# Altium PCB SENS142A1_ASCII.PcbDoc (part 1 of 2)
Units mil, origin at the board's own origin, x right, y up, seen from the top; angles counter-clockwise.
Board outline 2760 x 2518.85 mil, 4 copper layers (Top Layer, Signal Layer 1, Signal Layer 2, Bottom Layer), stack 62.2 mil thick; 50 components, 21 nets, 98 pads, 258 vias.
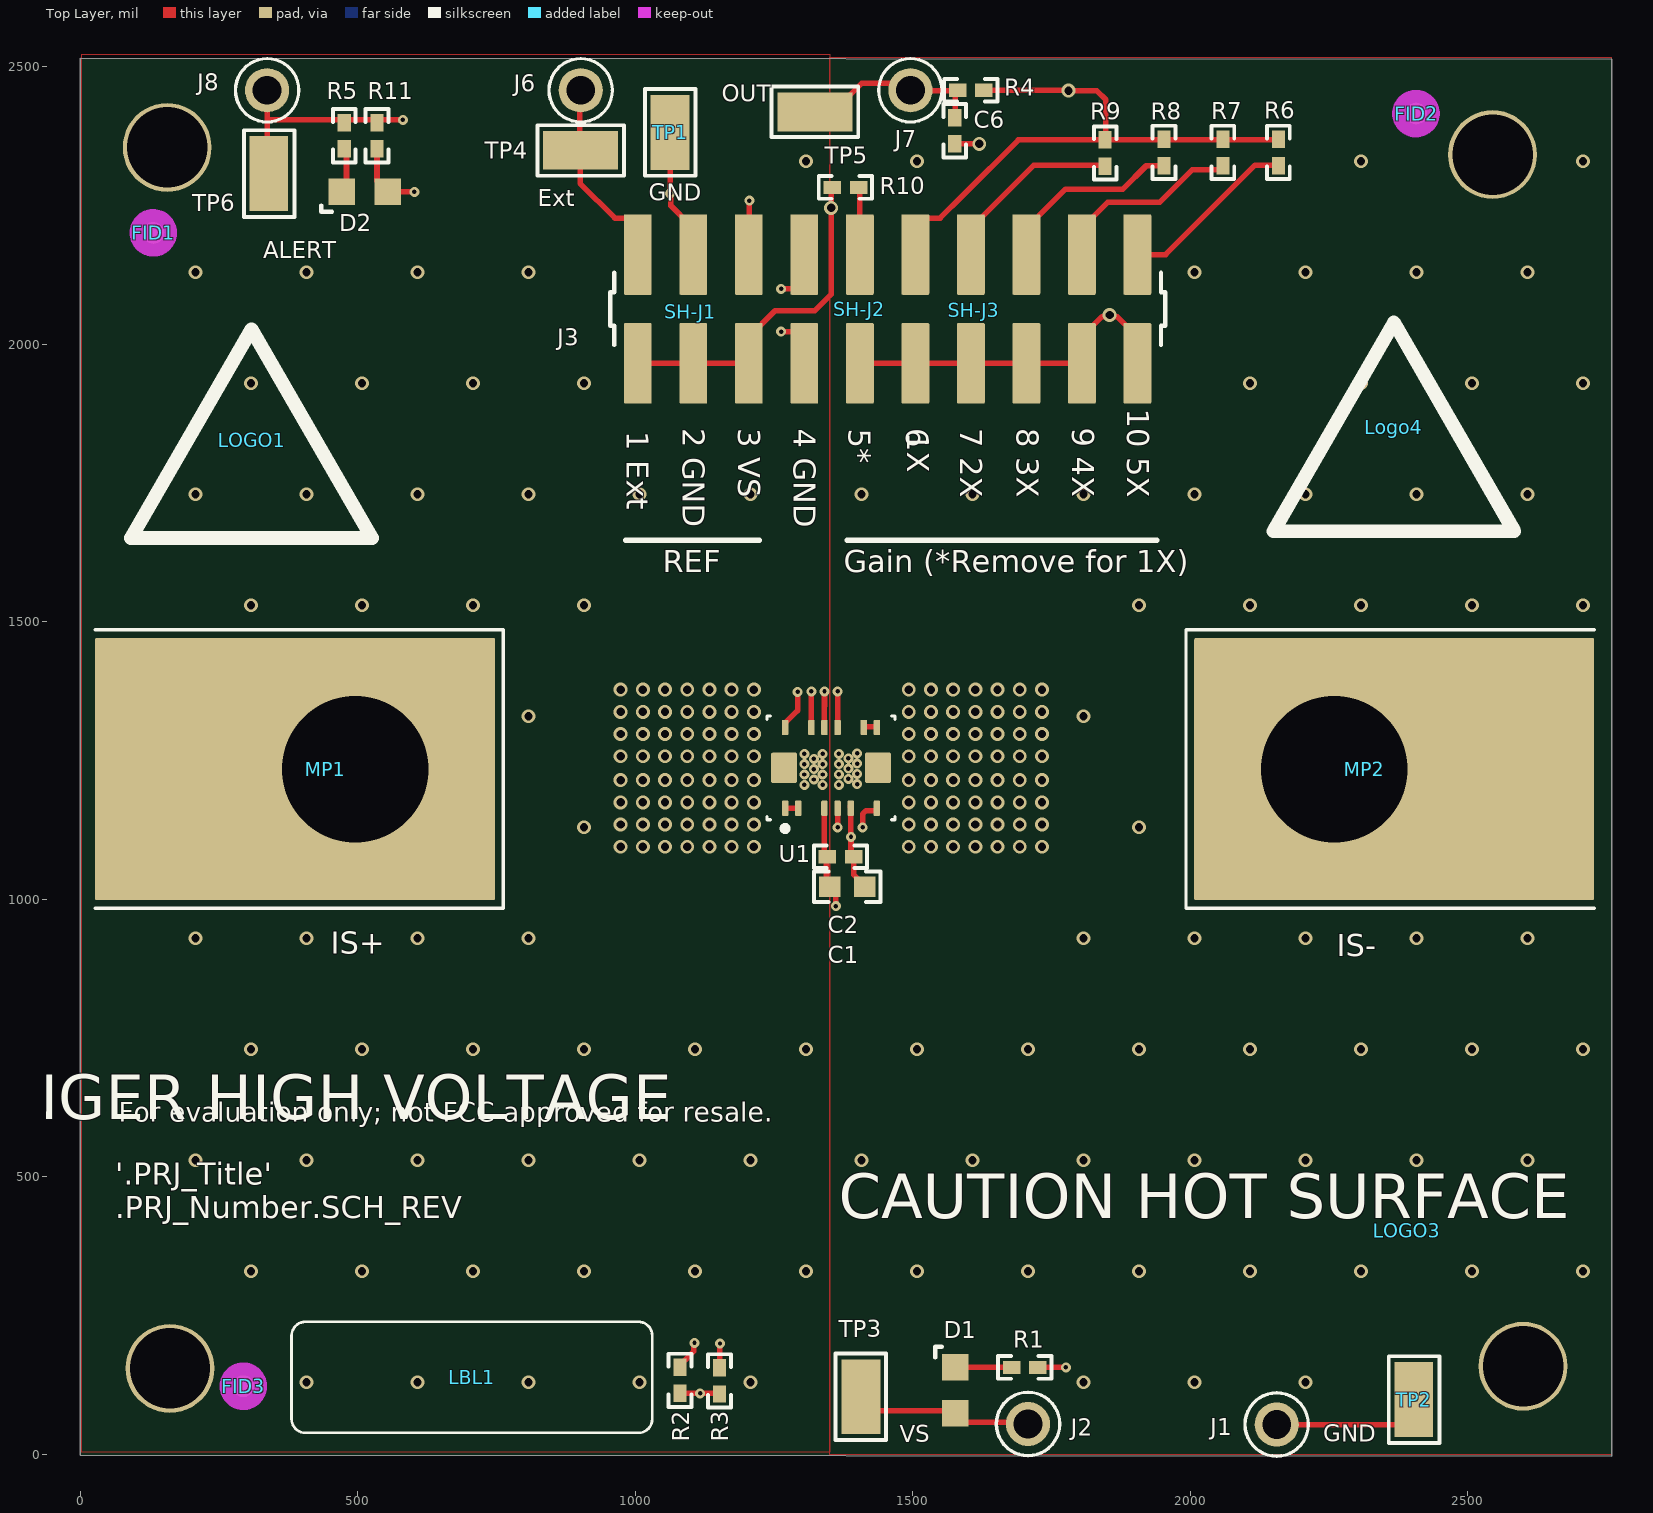
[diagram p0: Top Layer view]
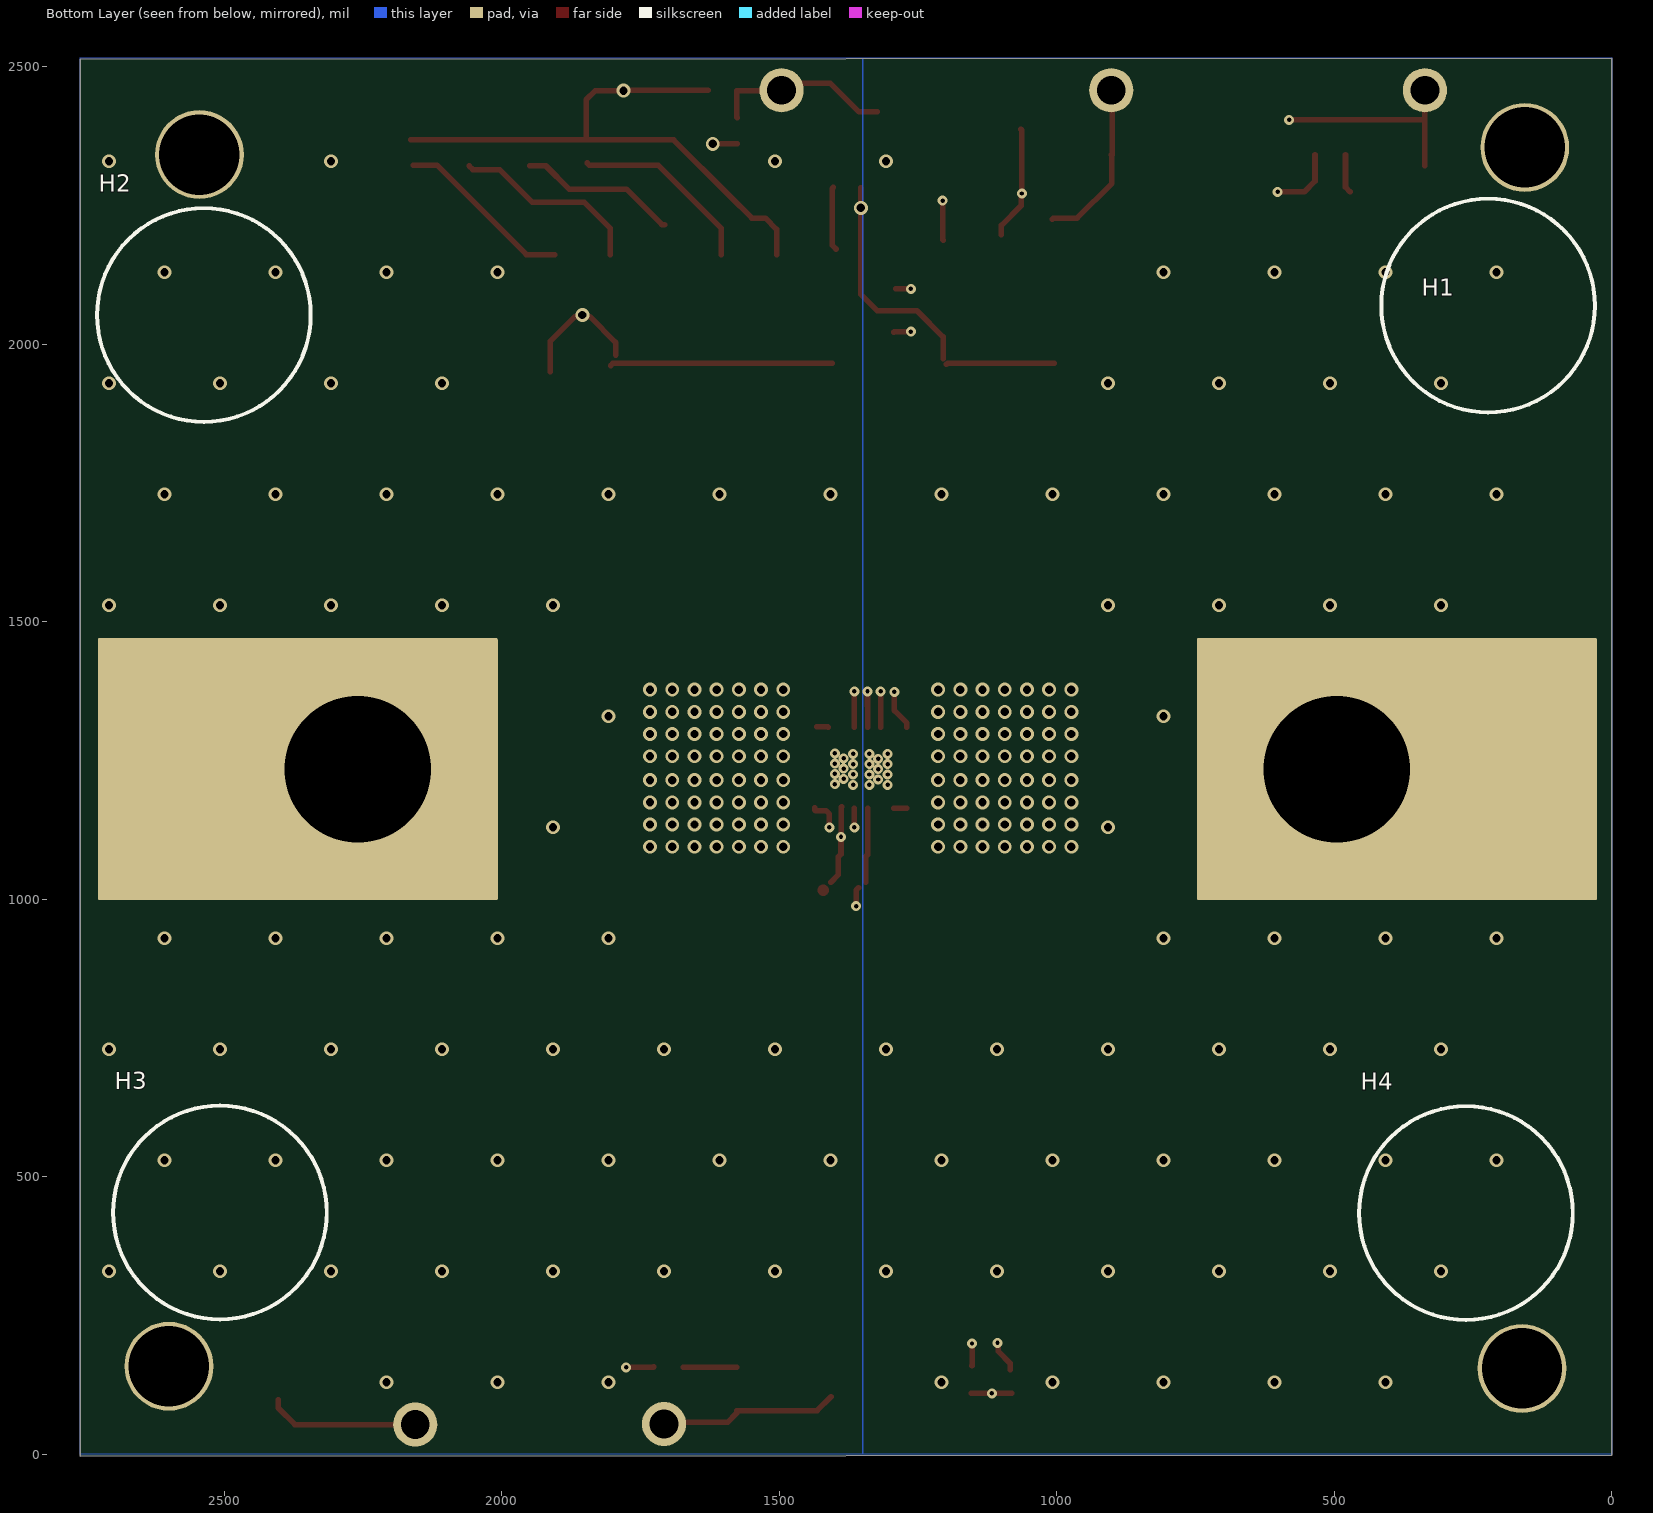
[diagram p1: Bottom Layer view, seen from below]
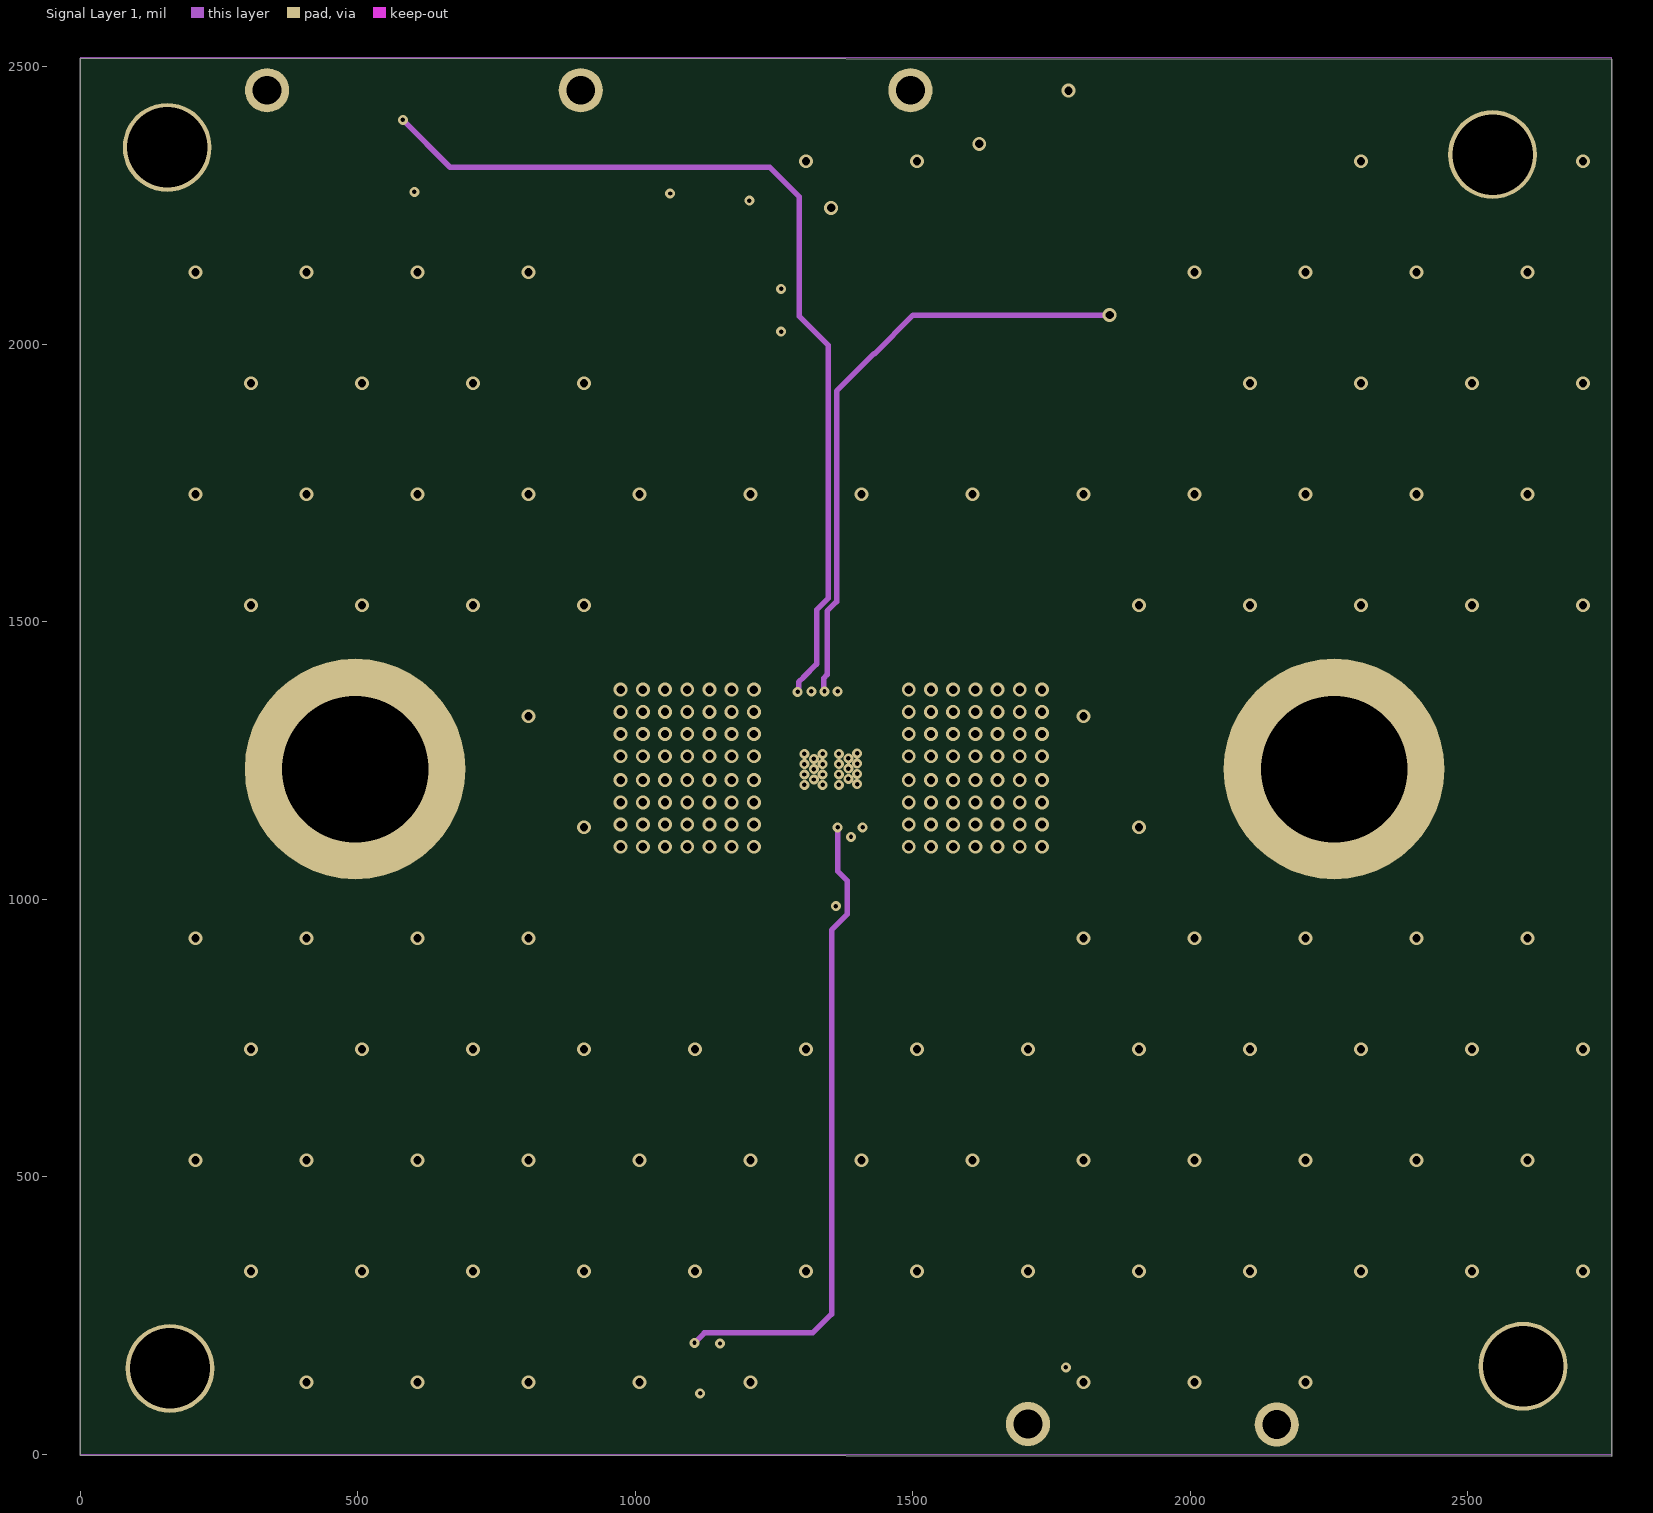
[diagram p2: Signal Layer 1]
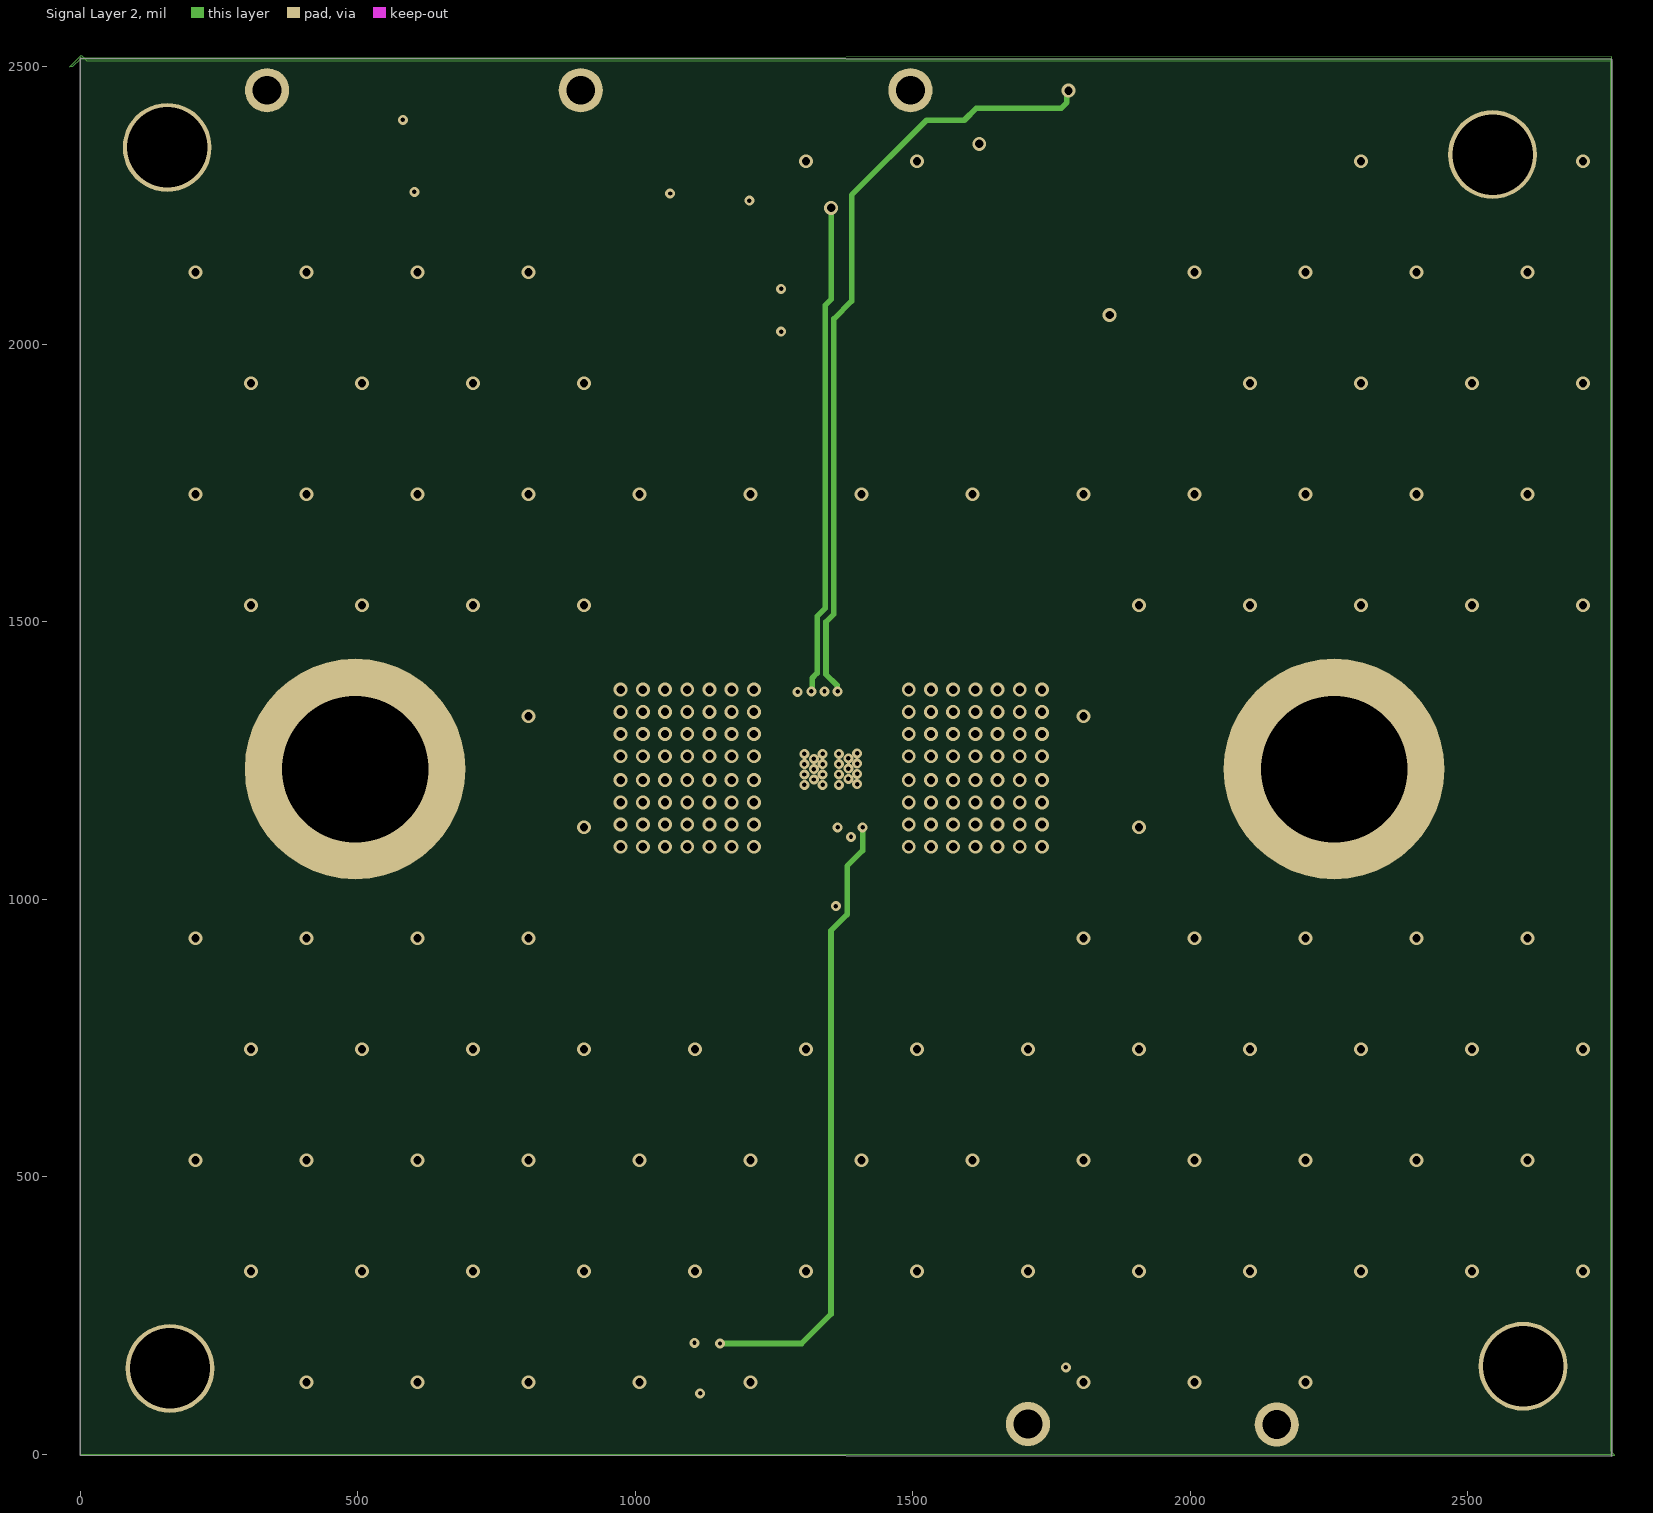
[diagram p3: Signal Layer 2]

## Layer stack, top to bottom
Top Solder: solder mask 0.4, Solder Resist, Dk 3.5
Top Layer: signal copper 2.8
Dielectric1: dielectric 17, FR-4, Dk 4.2
Signal Layer 1: signal copper 2.8
Dielectric 2: core 17, FR-4, Dk 4.2
Signal Layer 2: signal copper 2.8
Dielectric 3: dielectric 17, FR-4, Dk 4.2
Bottom Layer: signal copper 2.8
Bottom Solder: solder mask 0.4, Solder Resist, Dk 3.5

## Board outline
0,-1 0,2516 2760,2514.15 2760,-2.85

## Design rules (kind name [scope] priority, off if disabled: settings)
AcuteAngle [All] p0: scope1count=1 scope1_0_kind=Board scope1_0_value=Board scope2count=1 scope2_0_kind=Board scope2_0_value=Board commentlength=0 minimum=4.50000000000000E+0001
AcuteAngle [All] p1: minimum=4.50000000000000E+0001 checktracksonly=FALSE
AssemblyTestPointUsage [All] p0: scope1count=1 scope1_0_kind=Board scope1_0_value=Board scope2count=1 scope2_0_kind=Board scope2_0_value=Board commentlength=0
AssemblyTestPointUsage [All] p1: valid=2
AssemblyTestpoint [All] p0: scope1count=1 scope1_0_kind=Board scope1_0_value=Board scope2count=1 scope2_0_kind=Board scope2_0_value=Board commentlength=0
BoardOutlineClearance [All] p0 off: scope1count=1 scope1_0_kind=Board scope1_0_value=Board scope2count=1 scope2_0_kind=Board scope2_0_value=Board commentlength=172 gap=15 // Protel DXP Scope 1 Expression Was: OnCopper and Not InComponentClass('Logo') and not InComponentClass('FiducialMark') and not InRegion(1000,500,4000,800) and not InPoly
BoardOutlineClearance BoardOutlineClearance_Poly [All] p0 off: scope1count=1 scope1_0_kind=Board scope1_0_value=Board scope2count=1 scope2_0_kind=Board scope2_0_value=Board commentlength=58 gap=25 // Protel DXP Scope 1 Expression Was: OnCopper and IsPoly
BoardOutlineClearance BoardOutlineClearance_MountingHoles [All] p0 off: scope1count=1 scope1_0_kind=Board scope1_0_value=Board scope2count=1 scope2_0_kind=Board scope2_0_value=Board commentlength=86 gap=14 // Protel DXP Scope 1 Expression Was: OnCopper and InComponentClass('Mounting Holes')
BoardOutlineClearance BoardOutlineClearance_MountingHoles [OnCopper and InComponentClass('Mounting Holes')] p1: gap=14 ignorepadtopadclearanceinfootprint=FALSE
BoardOutlineClearance BoardOutlineClearance_Poly [OnCopper and IsPoly] p2: gap=25 ignorepadtopadclearanceinfootprint=FALSE
BoardOutlineClearance [OnCopper and Not InComponentClass('Logo') and not InComponentClass('FiducialMark') and not InRegion(1000,500,4000,800) and not InPoly] p3: gap=15 ignorepadtopadclearanceinfootprint=FALSE
Clearance Clearance_IS- [All] p0 off: scope1count=1 scope1_0_kind=Net scope1_0_value=IS- scope2count=1 scope2_0_kind=Board scope2_0_value=Board commentlength=350 gap=16 // Protel DXP Scope 2 Expression Was: (InNet('OUT') OR InNet('FB') OR InNet('REF') OR InNet('GND') OR InNet('VS') OR InNet('NC4') OR InNet('NC6') OR InNet('ALERT') OR InNet('NetD1_2') OR InNet('NetD2_2') OR InNet('NetJ3_10') OR InNet('NetJ3_14') OR InNet('NetJ3_16') OR InNet('NetJ3_18') OR InNet('NetJ3_20') OR InNet('OUT_FLT') OR InNet('Ext_REF'))
Clearance [All] p0: scope1count=1 scope1_0_kind=Board scope1_0_value=Board scope2count=1 scope2_0_kind=Board scope2_0_value=Board commentlength=0 gap=5
Clearance Clearance_FiducialMark [All] p0 off: scope1count=1 scope1_0_kind=Board scope1_0_value=Board scope2count=1 scope2_0_kind=Board scope2_0_value=Board commentlength=81 gap=0 // Protel DXP Scope 2 Expression Was: IsPad and InComponentClass('FiducialMark')
Clearance Clearance_IS+ [All] p0 off: scope1count=1 scope1_0_kind=Net scope1_0_value=IS+ scope2count=1 scope2_0_kind=Board scope2_0_value=Board commentlength=350 gap=16 // Protel DXP Scope 2 Expression Was: (InNet('OUT') OR InNet('FB') OR InNet('REF') OR InNet('GND') OR InNet('VS') OR InNet('NC4') OR InNet('NC6') OR InNet('ALERT') OR InNet('NetD1_2') OR InNet('NetD2_2') OR InNet('NetJ3_10') OR InNet('NetJ3_14') OR InNet('NetJ3_16') OR InNet('NetJ3_18') OR InNet('NetJ3_20') OR InNet('OUT_FLT') OR InNet('Ext_REF'))
Clearance Clearance_Keepouts [All] p0 off: scope1count=1 scope1_0_kind=Board scope1_0_value=Board scope2count=1 scope2_0_kind=Board scope2_0_value=Board commentlength=99 gap=0 // Protel DXP Scope 2 Expression Was: ((IsTrack Or IsArc) And Not InPoly) And IsFree and IsKeepOut
Clearance Clearance_Keepouts [((IsTrack Or IsArc) And Not InPoly) And IsFree and IsKeepOut vs ((IsTrack Or IsArc) And Not InPoly) And IsFree and IsKeepOut] p1: gap=0 ignorepadtopadclearanceinfootprint=FALSE
Clearance Clearance_IS+ [InNet('IS+') vs (InNet('OUT') OR InNet('FB') OR InNet('REF') OR InNet('GND') OR InNet('VS') OR InNet('NC4') OR InNet('NC6') OR InNet('ALERT') OR InNet('NetD1_2') OR InNet('NetD2_2') OR InNet('NetJ3_10') OR InNet('NetJ3_14') OR InNet('NetJ3_16') OR InNet('NetJ3_18') OR InNet('NetJ3_20') OR InNet('OUT_FLT') OR InNet('Ext_REF'))] p2: gap=16 ignorepadtopadclearanceinfootprint=TRUE
Clearance Clearance_IS- [InNet('IS-') vs (InNet('OUT') OR InNet('FB') OR InNet('REF') OR InNet('GND') OR InNet('VS') OR InNet('NC4') OR InNet('NC6') OR InNet('ALERT') OR InNet('NetD1_2') OR InNet('NetD2_2') OR InNet('NetJ3_10') OR InNet('NetJ3_14') OR InNet('NetJ3_16') OR InNet('NetJ3_18') OR InNet('NetJ3_20') OR InNet('OUT_FLT') OR InNet('Ext_REF'))] p3: gap=16 ignorepadtopadclearanceinfootprint=TRUE
Clearance Clearance_FiducialMark [IsKeepOut and InComponentClass('FiducialMark') vs IsPad and InComponentClass('FiducialMark')] p4: gap=0 ignorepadtopadclearanceinfootprint=FALSE
Clearance [All] p5: gap=5 ignorepadtopadclearanceinfootprint=TRUE
ComponentClearance [All] p0: scope1count=1 scope1_0_kind=Board scope1_0_value=Board scope2count=1 scope2_0_kind=Board scope2_0_value=Board commentlength=0 gap=30 collisioncheckmode=3
ComponentClearance ComponentClearance_THtoTH [All] p0 off: scope1count=1 scope1_0_kind=Board scope1_0_value=Board scope2count=1 scope2_0_kind=Board scope2_0_value=Board commentlength=54 gap=30 collisioncheckmode=3 // Protel DXP Scope 2 Expression Was: IsThruComponent
ComponentClearance ComponentClearance_THtoSMT [All] p0 off: scope1count=1 scope1_0_kind=Board scope1_0_value=Board scope2count=1 scope2_0_kind=Board scope2_0_value=Board commentlength=53 gap=40 collisioncheckmode=3 // Protel DXP Scope 2 Expression Was: IsSMTComponent
ComponentClearance ComponentClearance_SmallPassives [All] p0 off: scope1count=1 scope1_0_kind=Board scope1_0_value=Board scope2count=1 scope2_0_kind=Board scope2_0_value=Board commentlength=508 gap=14.96 collisioncheckmode=3 // Protel DXP Scope 2 Expression Was: HasFootprint('0201*') or HasFootprint('0402*') or HasFootprint('0508') or HasFootprint('0603*') or HasFootprint('0612') or HasFootprint('0805*') or HasFootprint('0815*') or HasFootprint('0830*') or HasFootprint('1206*') or HasFootprint('1210*') or HasFootprint('1808*') or HasFootprint('1812*') or HasFootprint('1825*') or HasFootprint('2010*') or HasFootprint('2220*') or HasFootprint('2225*') or HasFootprint('2512*') or HasFootprint('2728*') or HasFootprint('3518*')
ComponentClearance ComponentClearance_MountingHoles [All] p0: scope1count=1 scope1_0_kind=ComponentClass scope1_0_value="Mounting Holes" scope2count=1 scope2_0_kind=Board scope2_0_value=Board commentlength=0 gap=250 collisioncheckmode=3
ComponentClearance ComponentClearance_ScrewToNut [All] p0 off: scope1count=1 scope1_0_kind=Board scope1_0_value=Board scope2count=1 scope2_0_kind=Board scope2_0_value=Board commentlength=71 gap=5 collisioncheckmode=3 // Protel DXP Scope 2 Expression Was: (HasFootprint('Keystone_1902C'))
ComponentClearance ComponentClearance_Logo [All] p0: scope1count=1 scope1_0_kind=ComponentClass scope1_0_value=Logo scope2count=1 scope2_0_kind=Board scope2_0_value=Board commentlength=0 gap=20 collisioncheckmode=3
ComponentClearance ComponentClearance_Shunt [All] p0: scope1count=1 scope1_0_kind=ComponentClass scope1_0_value=Header scope2count=1 scope2_0_kind=ComponentClass scope2_0_value=Shunt commentlength=0 gap=0 collisioncheckmode=3
ComponentClearance ComponentClearance_MountingHoles_FiducialMarks [All] p0: scope1count=1 scope1_0_kind=ComponentClass scope1_0_value="Mounting Holes" scope2count=1 scope2_0_kind=ComponentClass scope2_0_value=FiducialMark commentlength=0 gap=50 collisioncheckmode=3
ComponentClearance ComponentClearance_MountingHoles_FiducialMarks [InComponentClass('Mounting Holes') vs InComponentClass('FiducialMark')] p1: gap=50 collisioncheckmode=3 verticalgap=10 showdistances=FALSE
ComponentClearance ComponentClearance_Shunt [InComponentClass('Header') vs InComponentClass('Shunt')] p2: gap=0 collisioncheckmode=3 verticalgap=0 showdistances=FALSE
ComponentClearance ComponentClearance_Logo [InComponentClass('Logo')] p3: gap=20 collisioncheckmode=3 verticalgap=10 showdistances=FALSE
ComponentClearance ComponentClearance_ScrewToNut [(HasFootprint('NY PMS 440 0025 PH')) vs (HasFootprint('Keystone_1902C'))] p4: gap=5 collisioncheckmode=3 verticalgap=10 showdistances=FALSE
ComponentClearance ComponentClearance_MountingHoles [InComponentClass('Mounting Holes')] p5: gap=250 collisioncheckmode=3 verticalgap=100000 showdistances=FALSE
ComponentClearance ComponentClearance_SmallPassives [HasFootprint('0201*') or HasFootprint('0402*') or HasFootprint('0508') or HasFootprint('0603*') or HasFootprint('0612') or HasFootprint('0805*') or HasFootprint('0815*') or HasFootprint('0830*') or HasFootprint('1206*') or HasFootprint('1210*') or HasFootprint('1808*') or HasFootprint('1812*') or HasFootprint('1825*') or HasFootprint('2010*') or HasFootprint('2220*') or HasFootprint('2225*') or HasFootprint('2512*') or HasFootprint('2728*') or HasFootprint('3518*') vs HasFootprint('0201*') or HasFootprint('0402*') or HasFootprint('0508') or HasFootprint('0603*') or HasFootprint('0612') or HasFootprint('0805*') or HasFootprint('0815*') or HasFootprint('0830*') or HasFootprint('1206*') or HasFootprint('1210*') or HasFootprint('1808*') or HasFootprint('1812*') or HasFootprint('1825*') or HasFootprint('2010*') or HasFootprint('2220*') or HasFootprint('2225*') or HasFootprint('2512*') or HasFootprint('2728*') or HasFootprint('3518*')] p6: gap=14.96 collisioncheckmode=3 verticalgap=10 showdistances=FALSE
ComponentClearance ComponentClearance_THtoSMT [IsThruComponent vs IsSMTComponent] p7: gap=40 collisioncheckmode=3 verticalgap=30 showdistances=FALSE
ComponentClearance ComponentClearance_THtoTH [IsThruComponent vs IsThruComponent] p8: gap=30 collisioncheckmode=3 verticalgap=30 showdistances=FALSE
ComponentClearance [All] p9: gap=30 collisioncheckmode=3 verticalgap=10 showdistances=FALSE
DiffPairsRouting [All] p0: scope1count=1 scope1_0_kind=Board scope1_0_value=Board scope2count=1 scope2_0_kind=Board scope2_0_value=Board commentlength=0
DiffPairsRouting [All] p1: maxlimit=100 minlimit=10 mostfreqgap=10 toplayer_minwidth=15 toplayer_maxwidth=15 toplayer_prefwidth=15 midlayer1_minwidth=15 midlayer1_maxwidth=15 midlayer1_prefwidth=15 midlayer2_minwidth=15 midlayer2_maxwidth=15 midlayer2_prefwidth=15 bottomlayer_minwidth=15 bottomlayer_maxwidth=15 bottomlayer_prefwidth=15 maxuncoupledlength=1000
FabricationTestPointUsage TestPointUsage [All] p0: scope1count=1 scope1_0_kind=Board scope1_0_value=Board scope2count=1 scope2_0_kind=Board scope2_0_value=Board commentlength=0 valid=2 allowmultiple=FALSE
FabricationTestPointUsage TestPointUsage [All] p1: valid=2 allowmultiple=FALSE
FabricationTestpoint Testpoint [All] p0: scope1count=1 scope1_0_kind=Board scope1_0_value=Board scope2count=1 scope2_0_kind=Board scope2_0_value=Board commentlength=0 side=3 testpointundercomponent=TRUE minsize=40 maxsize=100 preferedsize=60 minholesize=0 maxholesize=40 preferedholesize=32 testpointgrid=1
FabricationTestpoint Testpoint [All] p1: side=3 testpointundercomponent=TRUE minsize=40 maxsize=100 preferedsize=60 minholesize=0 maxholesize=40 preferedholesize=32 testpointgrid=1 allowsidetop=TRUE allowsidebottom=TRUE usegrid=TRUE gridtolerance=0.01
FanoutControl Fanout_Small [All] p0 off: scope1count=1 scope1_0_kind=Board scope1_0_value=Board scope2count=1 scope2_0_kind=Board scope2_0_value=Board commentlength=84 // Protel DXP Scope 1 Expression Was: (CompPinCount < 5)   Fanout_Small (Default Rule)
FanoutControl Fanout_Default [All] p0: scope1count=1 scope1_0_kind=Board scope1_0_value=Board scope2count=1 scope2_0_kind=Board scope2_0_value=Board commentlength=30 // Fanout_Default (Default Rule)
FanoutControl Fanout_SOIC [All] p0 off: scope1count=1 scope1_0_kind=Board scope1_0_value=Board scope2count=1 scope2_0_kind=Board scope2_0_value=Board commentlength=71 // Protel DXP Scope 1 Expression Was: IsSOIC   Fanout_SOIC (Default Rule)
FanoutControl Fanout_BGA [All] p0 off: scope1count=1 scope1_0_kind=Board scope1_0_value=Board scope2count=1 scope2_0_kind=Board scope2_0_value=Board commentlength=69 // Protel DXP Scope 1 Expression Was: IsBGA   Fanout_BGA (Default Rule)
FanoutControl Fanout_LCC [All] p0 off: scope1count=1 scope1_0_kind=Board scope1_0_value=Board scope2count=1 scope2_0_kind=Board scope2_0_value=Board commentlength=69 // Protel DXP Scope 1 Expression Was: IsLCC   Fanout_LCC (Default Rule)
FanoutControl Fanout_LCC [IsLCC] p1: bgadir=Out bgaviamode=Centered fanoutstyle=Auto fanoutdirection=Alternating viagrid=1 // Fanout_LCC (Default Rule)
FanoutControl Fanout_BGA [IsBGA] p2: bgadir=Out bgaviamode=Centered fanoutstyle=Auto fanoutdirection=Alternating viagrid=1 // Fanout_BGA (Default Rule)
FanoutControl Fanout_Default [All] p4: bgadir=Out bgaviamode=Centered fanoutstyle=Auto fanoutdirection=Alternating viagrid=1 // Fanout_Default (Default Rule)
FanoutControl Fanout_Small [(CompPinCount < 5)] p5: bgadir=Out bgaviamode=Centered fanoutstyle=Auto fanoutdirection=OutThenIn viagrid=1 // Fanout_Small (Default Rule)
Height [All] p0: scope1count=1 scope1_0_kind=Board scope1_0_value=Board scope2count=1 scope2_0_kind=Board scope2_0_value=Board commentlength=0
HoleSize [All] p0: scope1count=1 scope1_0_kind=Board scope1_0_value=Board scope2count=1 scope2_0_kind=Board scope2_0_value=Board commentlength=0 absolutevalues=TRUE maxlimit=251 minlimit=8 maxpercent=80.000 minpercent=20.000
HoleSize [All] p1: absolutevalues=TRUE maxlimit=251 minlimit=8 maxpercent=80.000 minpercent=20.000
HoleToHoleClearance [All] p0: scope1count=1 scope1_0_kind=Board scope1_0_value=Board scope2count=1 scope2_0_kind=Board scope2_0_value=Board commentlength=0
HoleToHoleClearance [All] p1: gap=8 allowstackedmicrovias=TRUE
LayerPairs [All] p0: scope1count=1 scope1_0_kind=Board scope1_0_value=Board scope2count=1 scope2_0_kind=Board scope2_0_value=Board commentlength=0 enforce=TRUE
MinimumAnnularRing [All] p0: scope1count=1 scope1_0_kind=Board scope1_0_value=Board scope2count=1 scope2_0_kind=Board scope2_0_value=Board commentlength=0 minimumring=5
MinimumAnnularRing MinimumAnnularRing_ThermalPadVias [All] p0 off: scope1count=1 scope1_0_kind=Board scope1_0_value=Board scope2count=1 scope2_0_kind=Board scope2_0_value=Board commentlength=63 minimumring=5 // Protel DXP Scope 1 Expression Was: IsVia and InAnyComponent
MinimumAnnularRing MinimumAnnularRing_ThermalPadVias [IsVia and InAnyComponent] p1: minimumring=5
MinimumAnnularRing [All] p2: minimumring=5
MinimumSolderMaskSliver [All] p0: scope1count=1 scope1_0_kind=Board scope1_0_value=Board scope2count=1 scope2_0_kind=Board scope2_0_value=Board commentlength=0
MinimumSolderMaskSliver MinimumSolderMaskSliver_Logo [All] p0: scope1count=1 scope1_0_kind=ComponentClass scope1_0_value=Logo scope2count=1 scope2_0_kind=ComponentClass scope2_0_value=Logo commentlength=0
MinimumSolderMaskSliver MinimumSolderMaskSliver_Logo [InComponentClass('Logo') vs InComponentClass('Logo')] p1: minsoldermaskwidth=0.7
MinimumSolderMaskSliver [All] p2: minsoldermaskwidth=4
NetAntennae [All] p0: scope1count=1 scope1_0_kind=Board scope1_0_value=Board scope2count=1 scope2_0_kind=Board scope2_0_value=Board commentlength=0
PasteMaskExpansion [All] p0: scope1count=1 scope1_0_kind=Board scope1_0_value=Board scope2count=1 scope2_0_kind=Board scope2_0_value=Board commentlength=0 expansion=0
PlaneClearance [All] p0: scope1count=1 scope1_0_kind=Board scope1_0_value=Board scope2count=1 scope2_0_kind=Board scope2_0_value=Board commentlength=0 clearance=20
PlaneConnect [All] p0: scope1count=1 scope1_0_kind=Board scope1_0_value=Board scope2count=1 scope2_0_kind=Board scope2_0_value=Board commentlength=0 planeconnectstyle=Relief reliefexpansion=10 reliefentries=4 reliefconductorwidth=10 reliefairgap=10
PlaneConnect [All] p1: planeconnectstyle=Relief reliefexpansion=10 reliefentries=4 reliefconductorwidth=10 reliefairgap=10
PolygonConnect [All] p0: scope1count=1 scope1_0_kind=Board scope1_0_value=Board scope2count=1 scope2_0_kind=Board scope2_0_value=Board commentlength=0 connectstyle=Direct reliefconductorwidth=10 reliefentries=4 polygonreliefangle="90 Angle"
PolygonConnect PolygonConnect_Trace [All] p0 off: scope1count=1 scope1_0_kind=Board scope1_0_value=Board scope2count=1 scope2_0_kind=Board scope2_0_value=Board commentlength=75 connectstyle=Direct reliefconductorwidth=10 reliefentries=4 polygonreliefangle="90 Angle" // Protel DXP Scope 1 Expression Was: InNet('NetJ1_5') OR InNet('NetJ1_3')
PolygonConnect PolygonConnect_Trace [InNet('NetJ1_5') OR InNet('NetJ1_3')] p1: connectstyle=Direct reliefconductorwidth=10 reliefentries=4 polygonreliefangle="90 Angle" airgapwidth=10
PolygonConnect [All] p2: thpad.connectstyle=Direct thpad.reliefconductorwidth=10 thpad.reliefentries=4 thpad.polygonreliefangle="90 Angle" thpad.airgapwidth=10 smdpad.connectstyle=Relief smdpad.reliefconductorwidth=10 smdpad.reliefentries=2 smdpad.polygonreliefangle="90 Angle" smdpad.airgapwidth=10 via.connectstyle=Direct via.reliefconductorwidth=10 via.reliefentries=4 via.polygonreliefangle="90 Angle" via.airgapwidth=10
RoutingCorners [All] p0: scope1count=1 scope1_0_kind=Board scope1_0_value=Board scope2count=1 scope2_0_kind=Board scope2_0_value=Board commentlength=0 cornerstyle=45-Degree minsetback=100 maxsetback=100
RoutingLayers [All] p0: scope1count=1 scope1_0_kind=Board scope1_0_value=Board scope2count=1 scope2_0_kind=Board scope2_0_value=Board commentlength=0 top layer=Automatic mid layer 1=Automatic mid layer 2=Automatic bottom layer=Automatic
RoutingPriority [All] p0: scope1count=1 scope1_0_kind=Board scope1_0_value=Board scope2count=1 scope2_0_kind=Board scope2_0_value=Board commentlength=0
RoutingTopology [All] p0: scope1count=1 scope1_0_kind=Board scope1_0_value=Board scope2count=1 scope2_0_kind=Board scope2_0_value=Board commentlength=0 topology=Shortest
RoutingVias [All] p0: scope1count=1 scope1_0_kind=Board scope1_0_value=Board scope2count=1 scope2_0_kind=Board scope2_0_value=Board commentlength=0 holewidth=10 width=20 viastyle="Through Hole" minholewidth=4 minwidth=15 maxholewidth=40 maxwidth=65
RoutingVias [All] p1: holewidth=10 width=20 viastyle="Through Hole" minholewidth=4 minwidth=15 maxholewidth=40 maxwidth=65
ShortCircuit [All] p0: scope1count=1 scope1_0_kind=Board scope1_0_value=Board scope2count=1 scope2_0_kind=Board scope2_0_value=Board commentlength=0 allowed=FALSE
SilkToBoardRegionClearance [All] p0 off: scope1count=1 scope1_0_kind=Board scope1_0_value=Board scope2count=1 scope2_0_kind=Board scope2_0_value=Board commentlength=130 // Protel DXP Scope 1 Expression Was: Not ((IsComment or IsDesignator) And (Hide <> 'False')) and not InRegion(1000,500,4000,800)
SilkToBoardRegionClearance [Not ((IsComment or IsDesignator) And (Hide <> 'False')) and not InRegion(1000,500,4000,800)] p1:
SilkToSilkClearance [All] p0: scope1count=1 scope1_0_kind=Board scope1_0_value=Board scope2count=1 scope2_0_kind=Board scope2_0_value=Board commentlength=0
SilkToSilkClearance SilkToSilkClearance_Pb-FreeLogo [All] p0 off: scope1count=1 scope1_0_kind=Board scope1_0_value=Board scope2count=1 scope2_0_kind=Board scope2_0_value=Board commentlength=120 // Protel DXP Scope 2 Expression Was: (HasFootprint('Pb-Free_Overlay_Medium') OR HasFootprint('Pb-Free_Overlay_Small'))
SilkToSilkClearance SilkToSilkClearance_Pb-FreeLogo [(HasFootprint('Pb-Free_Overlay_Medium') OR HasFootprint('Pb-Free_Overlay_Small')) vs (HasFootprint('Pb-Free_Overlay_Medium') OR HasFootprint('Pb-Free_Overlay_Small'))] p1: silktosilkclearance=0
SilkToSilkClearance [All] p2: silktosilkclearance=3.94
SilkToSolderMaskClearance "Silk to Solder Mask Opening" [All] p0: scope1count=1 scope1_0_kind=Board scope1_0_value=Board scope2count=1 scope2_0_kind=Board scope2_0_value=Board commentlength=0
SilkToSolderMaskClearance SilkToComponentPadClearance [All] p0 off: scope1count=1 scope1_0_kind=Board scope1_0_value=Board scope2count=1 scope2_0_kind=Board scope2_0_value=Board commentlength=87 // Protel DXP Scope 1 Expression Was: (IsPad or IsFill or IsRegion) and InAnycomponent
SilkToSolderMaskClearance SilkToComponentPadClearance [(IsPad or IsFill or IsRegion) and InAnycomponent] p1: minsilkscreentomaskgap=5 clearancetoexposedcopper=TRUE
SilkToSolderMaskClearance "Silk to Solder Mask Opening" [All] p2: minsilkscreentomaskgap=3.94 clearancetoexposedcopper=FALSE
SolderMaskExpansion [All] p0: scope1count=1 scope1_0_kind=Board scope1_0_value=Board scope2count=1 scope2_0_kind=Board scope2_0_value=Board commentlength=0 expansion=1.97
SolderMaskExpansion [All] p1: expansion=1.97 istentingtop=FALSE
UnRoutedNet [All] p0: scope1count=1 scope1_0_kind=Board scope1_0_value=Board scope2count=1 scope2_0_kind=Board scope2_0_value=Board commentlength=0
UnRoutedNet [All] p1: checkbadconnections=TRUE
UnpouredPolygon [All] p0: scope1count=1 scope1_0_kind=Board scope1_0_value=Board scope2count=1 scope2_0_kind=Board scope2_0_value=Board commentlength=0
Width [All] p0: scope1count=1 scope1_0_kind=Board scope1_0_value=Board scope2count=1 scope2_0_kind=Board scope2_0_value=Board commentlength=0 maxlimit=100 minlimit=5 preferedwidth=10
Width [All] p1: maxlimit=100 minlimit=5 preferedwidth=10 checkconnectedcopper=TRUE
13 further rules are at their usual default settings.

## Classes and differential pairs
component class Label: LBL1
component class Shunt: SH-J1 SH-J2 SH-J3
component class Header: J3
component class SENS142A1: "ALERT BUS" C1 C2 C6 D1 D2 J1 J2 J3 J6 J7 J8 MP1 MP2 q R1 R2 R3 R4 R5 R6 R7 R8 R9 R10 R11 SH-J1 SH-J2 SH-J3 SW2 SW? TP1 TP2 TP3 TP4 TP5 TP6 U1
component class SENS142A1_HW: FID1 FID2 FID3 H1 H2 H3 H4 LBL1 LOGO1 Logo2 LOGO3 Logo4 ZZ1 ZZ2 ZZ3 ZZ4
component class FiducialMark: FID1 FID2 FID3
component class AssemblyNote: ZZ1 ZZ2 ZZ3 ZZ4

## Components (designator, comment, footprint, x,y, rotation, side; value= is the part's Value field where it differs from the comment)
C1 "C1608X6S1H105K080AC" 0603 1382.19,1023 r0 top
C2 "GRM155R71H104ME14D" 0402 1370,1077 r0 top
C6 "CGA2B3X7S2A103K050BB" 0402 1576,2385 r90 top
D1 "POWER" VAOL-0805_White 1577,115.66 r90 top
D2 "ALERT" VAOL-0805_White 513,2275 r180 top
FID1 "Fiducial" Fiducial10-20 132,2201.12 r0 top
FID2 "Fiducial" Fiducial10-20 2407,2416 r0 top
FID3 "Fiducial" Fiducial10-20 294,123 r0 top
H1 "SJ61A2" Bumpon_SJ61A2 223,2070 r180 bottom
H2 "SJ61A2" Bumpon_SJ61A2 2537,2053 r180 bottom
H3 "SJ61A2" Bumpon_SJ61A2 2508,436 r180 bottom
H4 "SJ61A2" Bumpon_SJ61A2 263,435 r180 bottom
J1 "" FP-3-331272-8_PIN_RCPT-MFG 2156,54 r0 top
J2 "" FP-3-331272-8_PIN_RCPT-MFG 1708,55 r180 top
J3 "TSM-110-01-L-DV-P" CONN_TSM-110-01-T-DV-P 1455,2064 r90 top
J6 "" FP-3-331272-8_PIN_RCPT-MFG 902,2458 r0 top
J7 "" FP-3-331272-8_PIN_RCPT-MFG 1496,2458 r0 top
J8 "" FP-3-331272-8_PIN_RCPT-MFG 337,2458 r0 top
LBL1 "THT-14-423-10" Label_650x200 706,139 r180 top
LOGO1 "DANGER HIGH VOLTAGE" IEC_HighVoltage_Medium 309,1827 r0 top
Logo2 "FCC disclaimer" FCC_disclaimer 3340,617.12 r90 top
LOGO3 "CE Mark" CE_Mark_5mm 2390,403 r0 top
Logo4 "CAUTION HOT SURFACE" IEC_HotSurface_Medium 2367,1851 r0 top
MP1 "CB70-14-190" FP-CB70-14-190_CONN_TERM_RECT_LUG-MFG -30,1235 r0 top
MP2 "CB70-14-190" FP-CB70-14-190_CONN_TERM_RECT_LUG-MFG 2785,1235 r180 top
R1 "CRCW040210K0FKED" 0402 1702,157 r180 top
R2 "RC0402JR-070RL" 0402 1081,133.62 r270 top
R3 "RC0402JR-070RL" 0402 1152,132.62 r270 top
R4 "RC0402JR-070RL" 0402 1605,2458 r180 top
R5 "CRCW040210K0FKED" 0402 476,2376 r90 top
R6 "CRCW040220K0FKED" 0402 2159,2346 r270 top
R7 "CRCW040215K0FKED" 0402 2059,2346 r270 top
R8 "CRCW040210K0FKED" 0402 1953,2346 r90 top
R9 "CRCW04024K99FKED" 0402 1847,2345 r270 top
R10 "CRCW04024K99FKED" 0402 1379,2283 r0 top
R11 "CRCW040210K0FKED" 0402 535,2376 r90 top
SH-J1 "SPC02SYAN" SPC02SYAN 1099,2059 r270 top
SH-J2 "SPC02SYAN" SPC02SYAN 1404,2063 r90 top
SH-J3 "SPC02SYAN" SPC02SYAN 1610,2062 r90 top
TP1 "GND" Testpoint_Keystone_Miniature 1063,2382 r90 top
TP2 "GND" Testpoint_Keystone_Miniature 2403,99 r90 top
TP3 "VS" Testpoint_Keystone_Miniature 1407,104 r270 top
TP4 "Ext_REF" Testpoint_Keystone_Miniature 902,2350 r0 top
TP5 "OUT" Testpoint_Keystone_Miniature 1324,2419 r180 top
TP6 "" Testpoint_Keystone_Miniature 340,2308 r90 top
U1 "INA750AIREMR" REM0014B-MFG 1353,1237.12 r90 top
ZZ1 "This Assembly Note is for PCB labels only" AssemblyNoteLabel -115,3802.12 r0 top
ZZ2 "These assemblies are ESD sensitive, ESD precautions shall be observed." AssemblyNote -115,3693.24 r0 top
ZZ3 "These assemblies must be clean and free from flux and all contaminants. Use of no clean flux is not acceptable." AssemblyNote -115,3604.68 r0 top
ZZ4 "These assemblies must comply with workmanship standards IPC-A-610 Class 2, unless otherwise specified." AssemblyNote -115,3516.12 r0 top

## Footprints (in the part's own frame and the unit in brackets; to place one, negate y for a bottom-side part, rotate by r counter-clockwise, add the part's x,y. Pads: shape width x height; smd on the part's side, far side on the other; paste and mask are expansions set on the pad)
0402 [mm] "0402 from SM-752 data"
  rect 0.8x0.6 smd: 1(-0.6,0) 2(0.6,0)
  silkscreen extent -1.22,-0.52 1.22,0.52
0603 [mm] "0603 from SM-752 data"
  rect 1x0.95 smd: 1(-0.8,0) 2(0.8,0)
  silkscreen extent -1.52,-0.69 1.52,0.69
AssemblyNote [mil] "Assembly Note"
AssemblyNoteLabel [mil] "Assembly Note for PCB Labels"
Bumpon_SJ61A2 [mil] "3M Hemispherical Bumpon transparent"
  round 1 on Mech4: 0(0,0)
  silkscreen extent -192,-192 192,192
CE_Mark_5mm [mil] "Minimum text height for CE Mark"
CONN_TSM-110-01-T-DV-P [mil]
  rrect8% 145x50 smd: 1(-98,450) 2(98,450) 3(-98,350) 4(98,350) 5(-98,250) 6(98,250) 7(-98,150) 8(98,150) 9(-98,50) 10(98,50) 11(-98,-50) 12(98,-50) 13(-98,-150) 14(98,-150) 15(-98,-250) 16(98,-250) 17(-98,-350) 18(98,-350) 19(-98,-450) 20(98,-450)
  silkscreen extent -65,-500 65,500
FCC_disclaimer [mil]
Fiducial10-20 [mm]
  round 1 smd mask+0: 1(0,0)
  Top Layer keep-out circle w1.178: c0,0 r0.5
FP-3-331272-8_PIN_RCPT-MFG [mm]
  round 2.02 hole 1.32 paste-1000 mask+0: 1(0,0)
  silkscreen extent -1.45,-1.45 1.45,1.45
FP-CB70-14-190_CONN_TERM_RECT_LUG-MFG [mm]
  rrect1% 18.3x12 smd paste-1000 mask+0: 1(10.6,0)
  rrect1% 18.3x12 smd far side paste-1000 mask+0: 1(10.6,0)
  round 10.1 hole 6.7 unplated paste+0 mask+0: 1(13.35,0)
  silkscreen extent 1.45,-6.38 20.12,6.38
IEC_HighVoltage_Medium [mil]
  silkscreen extent -217,-176 217,200
IEC_HotSurface_Medium [mil]
  silkscreen extent -217,-188 217,188
Label_650x200 [mil] "Thermal Transfer Label"
  round 1 on Mech13: 0(0,0)
  silkscreen extent -325,-100 325,100
REM0014B-MFG [mm]
  rrect33% 0.7x0.3 smd paste+0 mask+0: 1(-1.85,2.1) 2(-1.85,1.5) 3(-1.85,0.3) 4(-1.85,-0.3) 5(-1.85,-0.9) 6(-1.85,-2.1) 8(1.85,-2.1) 9(1.85,-1.5) 10(1.85,-0.3) 11(1.85,0.3) 12(1.85,0.9) 13(1.85,2.1)
  rrect17% 1.4x1.2 smd paste-1000 mask+0: 7(0,-2.15) 14(0,2.15)
  silkscreen extent -2.9,-2.93 2.37,2.93
SPC02SYAN [mil] "SULLINS"
  round 1 on Mech3: 0(0,0)
Testpoint_Keystone_Miniature [mil] "Miniature SMT test point"
  rect 135x70 smd: 1(0,0)
  silkscreen extent -78,-46 78,45
VAOL-0805_White [mm] "Visual Communications"
  rect 1.2x1.2 smd: 1(-1.05,0) 2(1.05,0)
  silkscreen extent 1.5,0.63 2,0.91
